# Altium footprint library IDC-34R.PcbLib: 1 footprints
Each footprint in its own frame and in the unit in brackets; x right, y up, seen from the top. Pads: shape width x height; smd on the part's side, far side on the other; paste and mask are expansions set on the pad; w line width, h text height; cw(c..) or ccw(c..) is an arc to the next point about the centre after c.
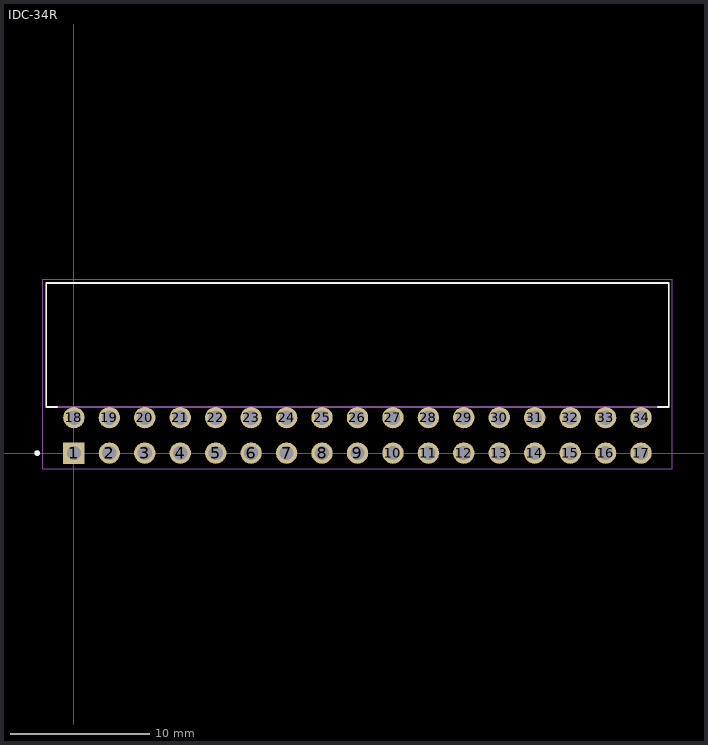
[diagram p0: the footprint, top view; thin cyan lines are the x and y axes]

## IDC-34R [mm]
pads (34):
  rect 1.53x1.53 hole 1.02: 1(0,0)
  round 1.53 hole 1.02: 2(2.54,0) 3(5.08,0) 4(7.62,0) 5(10.16,0) 6(12.7,0) 7(15.24,0) 8(17.78,0) 9(20.32,0) 10(22.86,0) 11(25.4,0) 12(27.94,0) 13(30.48,0) 14(33.02,0) 15(35.56,0) 16(38.1,0) 17(40.64,0) 18(0,2.54) 19(2.54,2.54) 20(5.08,2.54) 21(7.62,2.54) 22(10.16,2.54) 23(12.7,2.54) 24(15.24,2.54) 25(17.78,2.54) 26(20.32,2.54) 27(22.86,2.54) 28(25.4,2.54) 29(27.94,2.54) 30(30.48,2.54) 31(33.02,2.54) 32(35.56,2.54) 33(38.1,2.54) 34(40.64,2.54)
Top Overlay:
  circle w0.2: c-2.63,0 r0.1
  lines w0.127: -1.217,3.3 -1.98,3.3 -1.98,12.19 42.62,12.19 42.62,3.3 41.857,3.3
Mechanical 13:
  circle w0.2: c-2.63,0 r0.1
  lines w0.127: -1.98,3.3 -1.98,12.19 ; -1.98,3.3 42.62,3.3 ; -1.98,3.3 -1.98,12.19 ; -1.98,12.19 42.62,12.19 ; -1.98,12.19 42.62,12.19 ; 42.62,3.3 42.62,12.19 ; 42.62,3.3 42.62,12.19
Mechanical 15:
  lines w0.05: -2.23,-1.105 42.87,-1.105 42.87,12.44 -2.23,12.44 -2.23,-1.105
3D body "IDC-34R.STP": height 9.02, standoff -3.1, extent -5.08,-0.191 45.72,12.319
